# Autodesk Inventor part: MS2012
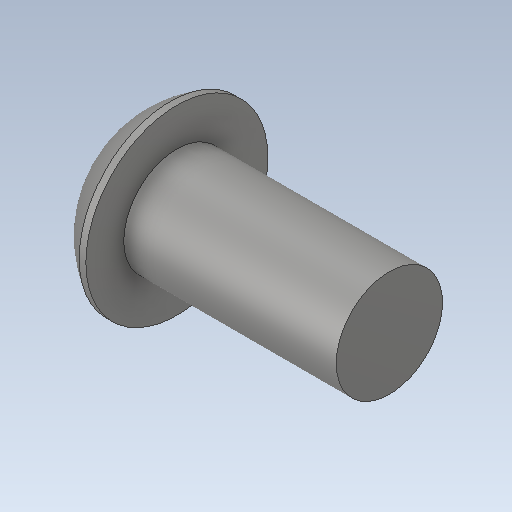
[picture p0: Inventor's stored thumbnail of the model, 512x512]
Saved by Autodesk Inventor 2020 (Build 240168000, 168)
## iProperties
Created: 2015-11
Part Number: MS2012
Material: Ogólny
Document SubType Name: Modeling
Designer: Tomasz
Density: 1 g/cm^3
Appearance: Domyślna
Sending System: SolidWorks 2017
Last Author: Tomasz
Last Saved: 2017-09-17
Author: Tomasz
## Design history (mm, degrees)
feature "Imported1"
node "Bryła1"
